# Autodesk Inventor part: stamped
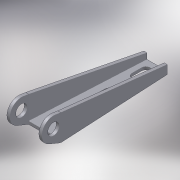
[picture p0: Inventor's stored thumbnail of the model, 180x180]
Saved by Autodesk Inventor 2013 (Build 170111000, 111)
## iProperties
Shininess: 25.0
Length Units: 11269
Angle Units: 11279
Time Units: 11290
Mass Units: 11283
Length Display Precision: 3
Angle Display Precision: 2
Created: 2002-03
Part Number: stamped
Material: Steel, Mild
Document SubType Name: Modeling
Designer: =<Author>
Density: 7.86 g/cm^3
Description: =<Part Number>
Density: 7.86
Volumn: 2.7250455516094187
Area: 40.68297056326448
PropertySet Name: Model Information
Control State: 0
Master: False
Checked Out: True
Last Check In Date: 2008-10-15
Checked Out Date: 2008-10-15
Author: LAlexey
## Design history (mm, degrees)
sketch "Sketch1"
  geometry: L1 (-27.14, 34.137)-(-30.14, -23.863); L2 (-30.14, -23.863)-(-12.14, -23.863); L3 (-12.14, -23.863)-(-15.14, 34.137); L4 (-15.14, 34.137)-(-27.14, 34.137)
  constraints: 8 end point, 2 horizontal, 1 equal length
  dimensions: "d0" = 12 distance of L3.end L1.start; "d1" = 18 distance of L1.end L2.end; "d2" = 58 distance between parallel lines of L2 L4
extrude "Extrusion1" new body sketch "Sketch1" distance "d3" = 1.5; taper "d4" = 0 deg
sketch "Sketch2"
  geometry: L1 (1.5, -58.078)-(1.5, 0) reference; L2 (0, -58.078)-(1.5, -58.078) reference; L3 (1.5, 0)-(4.5, 0); L4 (4.5, 0)-(13.5, -58.078); L5 (13.5, -58.078)-(1.5, -58.078)
  constraints: 6 end point, 2 parallel
  dimensions: "d5" = 12 distance of L4.end L1.start; "d6" = 3 distance of L1.end L3.end
extrude "Extrusion2" join sketch "Sketch2" distance "d7" = 1.5; taper "d8" = 0 deg
sketch "Sketch3"
  geometry: L1 (0, 58.078)-(0, 0) reference; L2 (1.5, 58.078)-(0, 58.078) reference; L3 (0, 0)-(-12, 0); L4 (-12, 0)-(-3, 58.078); L5 (-3, 58.078)-(0, 58.078)
  constraints: 6 end point, 2 parallel
  dimensions: "d9" = 3 distance of L4.end L1.start; "d10" = 12 distance of L1.end L3.end
extrude "Extrusion3" join sketch "Sketch3" distance "d11" = 1.5; taper "d12" = 0 deg
workplane "Work Plane1"
workplane "Work Plane2"
workplane "Work Plane3"
sketch "Sketch4"
  geometry: L1 (58, -13.5)-(0, -13.5) reference; L2 (58, -9)-(0, 0) reference; L3 (0, -13.5)-(-5.965, -11.05); L4 (0, 0)-(-2.765, 0.429); L5 (58, -12)-(58, -9) reference; L6 (58, -13.5)-(58, -12) reference; L7 (0, 0)-(0, -13.5); L8 (0, 0)-(0, -12) reference; C1 r 3 at (-3.685, -5.5); A1 r 6 centre (-3.685, -5.5) between (-2.765, 0.429) and (-5.965, -11.05)
  constraints: 6 end point, 2 centre point, 2 collinear, 2 point on circle, 1 coincident
  dimensions: "d17" = 6 radius of A1; "d18" = 6 diameter of C1; "d19" = 8 distance from line of L1 A1.centre; "d21" = 61.68497 distance from line of A1.centre L5
extrude "Extrusion4" join sketch "Sketch4" stored distance "d22" = 1.5; taper "d23" = 0 deg
sketch "Sketch5"
  geometry: L1 (30.14, -23.863)-(12.14, -23.863) reference; L2 (28.64, -23.863)-(28.64, -41.406); L3 (28.64, -41.406)-(13.64, -41.406); L4 (13.64, -41.406)-(13.64, -23.863); L5 (30.14, -29.828)-(30.14, -23.863) reference; L6 (12.14, -23.863)-(12.14, -29.828) reference
  constraints: 6 end point, 3 parallel, 2 point on line
  dimensions: "d24" = 1.5 distance between parallel lines of L5 L2; "d25" = 1.5 distance between parallel lines of L6 L4
extrude "Extrusion5" cut sketch "Sketch5" distance "d26" = 50; taper "d27" = 0 deg
sketch "Sketch6"
  geometry: L1 (15.14, 34.137)-(27.14, 34.137) reference; L2 (30.14, -23.863)-(28.64, -23.863) reference; L3 (18.89, 24.137)-(18.89, 29.137); L4 (23.39, 29.137)-(23.39, 24.137); L5 (15.14, 34.137)-(12.14, -23.863) reference; L6 (12.14, -23.863)-(12.14, -29.828) reference; L7 (30.14, -29.828)-(30.14, -23.863) reference; L8 (18.89, 5.137)-(18.89, 10.137); L9 (23.39, 10.137)-(23.39, 5.137); A1 r 2.25 centre (21.14, 29.137) between (23.39, 29.137) and (18.89, 29.137); A2 r 2.25 centre (21.14, 24.137) between (18.89, 24.137) and (23.39, 24.137); A3 r 2.25 centre (21.14, 10.137) between (23.39, 10.137) and (18.89, 10.137); A4 r 2.25 centre (21.14, 5.137) between (18.89, 5.137) and (23.39, 5.137)
  constraints: 8 end point, 8 point on circle, 8 tangent, 4 centre point, 2 collinear, 2 parallel, 1 perpendicular
  dimensions: "d28" = 4.5 distance between parallel lines of L4 L3; "d29" = 9 distance from line of L6 A2.centre; "d30" = 5 distance of A2.centre A1.centre; "d31" = 5 distance from line of L1 A1.centre; "d34" = 5 distance of A4.centre A3.centre; "d35" = 19 distance of A3.centre A1.centre
extrude "Extrusion6" cut sketch "Sketch6" distance "d36" = 50; taper "d37" = 0 deg
workaxis "Work Axis1"
workaxis "Work Axis2"
workplane "Work Plane4"
body "Solid1"
other parameters: "d13" = 90 deg, "d14" = 90 deg, "d15" = 90 deg, "d16" = 90 deg
